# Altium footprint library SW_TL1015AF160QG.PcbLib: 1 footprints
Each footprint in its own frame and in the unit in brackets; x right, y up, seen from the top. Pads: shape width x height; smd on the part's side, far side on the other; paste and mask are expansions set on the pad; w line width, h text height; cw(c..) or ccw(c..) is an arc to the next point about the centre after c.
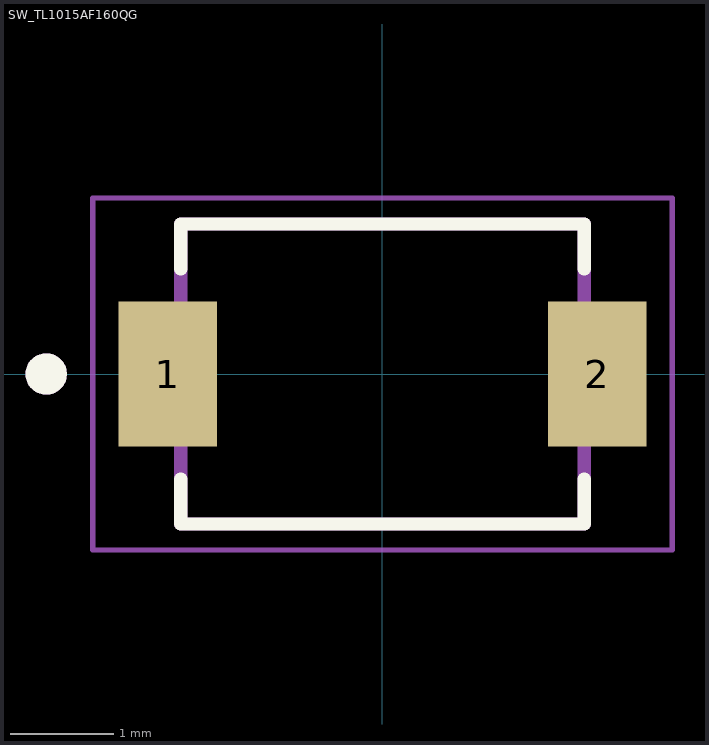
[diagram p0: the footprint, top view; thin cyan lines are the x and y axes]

## SW_TL1015AF160QG [mm]
pads (2):
  rect 0.95x1.4 smd: 1(-2.075,0) 2(2.075,0)
Top Overlay:
  circle w0.2: c-3.25,0 r0.1
  lines w0.127: -1.95,-1.014 -1.95,-1.45 1.95,-1.45 1.95,-1.014 ; -1.95,1.014 -1.95,1.45 1.95,1.45 1.95,1.014
Mechanical 13:
  circle w0.2: c-3.25,0 r0.1
  lines w0.127: -1.95,-1.45 1.95,-1.45 1.95,1.45 -1.95,1.45 -1.95,-1.45
Mechanical 15:
  lines w0.05: -2.8,-1.7 2.8,-1.7 2.8,1.7 -2.8,1.7 -2.8,-1.7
